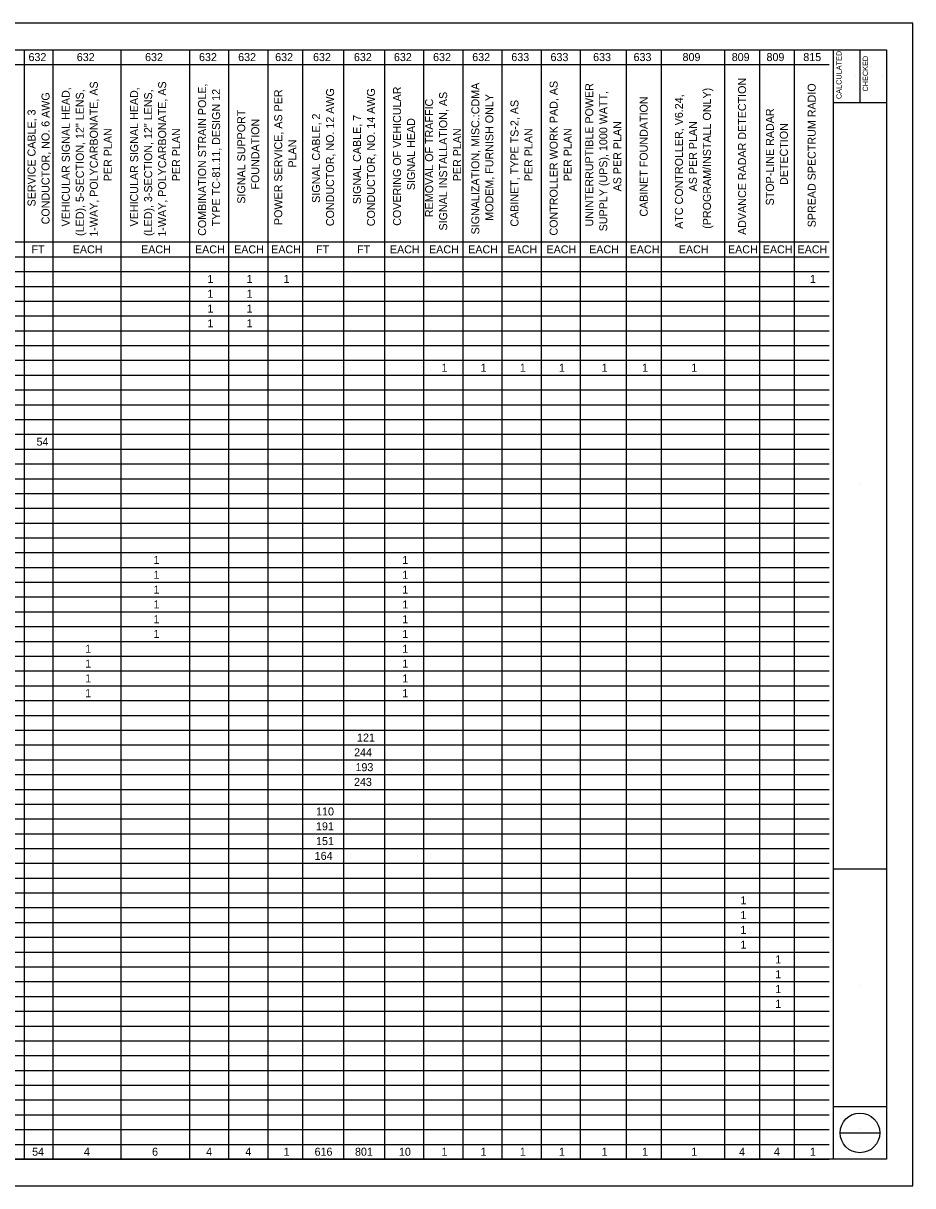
# Model space of a CAD drawing. Extents: x 43.5 to 77.5, y 34.1 to 56.1.
# Drawn here: x 60.62 to 77.46, y 34.09 to 56.09 of the extents above; entities that cross this region are included whole.
import ezdxf

# ---------------------------------------------------------------- set-up
doc = ezdxf.new("R2010")
doc.units = 0
for name, color, linetype in [('SH_Border', 7, 'Continuous'), ('SH_Cut_Line', 7, 'Continuous'), ('SH_Data', 7, 'Continuous'), ('SH_Text', 7, 'Continuous')]:
    doc.layers.add(name, color=color, linetype=linetype)

msp = doc.modelspace()

# ---------------------------------------------------------------- linework, layer by layer
at = {"layer": 'SH_Border'}
for p, q in [((45.459, 55.586), (75.875, 55.586)), ((60.642, 55.586), (60.642, 34.589)), ((61.186, 55.586), (61.186, 34.589)), ((62.47, 55.586), (62.47, 34.589)), ((63.771, 55.586), (63.771, 34.589)), ((64.512, 55.586), (64.512, 34.589)), ((65.253, 55.586), (65.253, 34.589)), ((65.912, 55.586), (65.912, 34.589)), ((66.686, 55.586), (66.686, 34.589)), ((67.46, 55.586), (67.46, 34.589)), ((68.201, 55.586), (68.201, 34.589)), ((68.942, 55.586), (68.942, 34.589)), ((69.683, 55.586), (69.683, 34.589)), ((70.424, 55.586), (70.424, 34.589)), ((71.165, 55.586), (71.165, 34.589)), ((72.038, 55.586), (72.038, 34.589)), ((72.697, 55.586), (72.697, 34.589)), ((73.899, 55.586), (73.899, 34.589)), ((74.558, 55.586), (74.558, 34.589)), ((75.216, 55.586), (75.216, 34.589)), ((75.959, 34.586), (75.959, 55.586)), ((76.459, 55.586), (76.459, 54.586)), ((52.029, 55.306), (75.875, 55.306)), ((75.959, 54.586), (76.959, 54.586)), ((52.029, 51.947), (75.875, 51.947)), ((45.459, 51.667), (75.875, 51.667)), ((45.459, 51.387), (75.875, 51.387)), ((45.459, 51.107), (75.875, 51.107)), ((45.459, 50.827), (75.875, 50.827)), ((45.459, 50.547), (75.875, 50.547)), ((45.459, 50.267), (75.875, 50.267)), ((45.459, 49.987), (75.875, 49.987)), ((45.459, 49.707), (75.875, 49.707)), ((45.459, 49.427), (75.875, 49.427)), ((45.459, 49.147), (75.875, 49.147)), ((45.459, 48.867), (75.875, 48.867)), ((45.459, 48.587), (75.875, 48.587)), ((45.459, 48.307), (75.875, 48.307)), ((45.459, 48.027), (75.875, 48.027)), ((45.459, 47.747), (75.875, 47.747)), ((45.459, 47.467), (75.875, 47.467)), ((45.459, 47.187), (75.875, 47.187)), ((45.459, 46.908), (75.875, 46.908)), ((45.459, 46.628), (75.875, 46.628)), ((45.459, 46.348), (75.875, 46.348)), ((45.459, 46.068), (75.875, 46.068)), ((45.459, 45.788), (75.875, 45.788)), ((45.459, 45.508), (75.875, 45.508)), ((45.459, 45.228), (75.875, 45.228)), ((45.459, 44.948), (75.875, 44.948)), ((45.459, 44.668), (75.875, 44.668)), ((45.459, 44.388), (75.875, 44.388)), ((45.459, 44.108), (75.875, 44.108)), ((45.459, 43.828), (75.875, 43.828)), ((45.459, 43.548), (75.875, 43.548)), ((45.459, 43.268), (75.875, 43.268)), ((45.459, 42.988), (75.875, 42.988)), ((45.459, 42.708), (75.875, 42.708)), ((45.459, 42.428), (75.875, 42.428)), ((45.459, 42.148), (75.875, 42.148)), ((45.459, 41.868), (75.875, 41.868)), ((45.459, 41.588), (75.875, 41.588)), ((45.459, 41.308), (75.875, 41.308)), ((45.459, 41.028), (75.875, 41.028)), ((45.459, 40.748), (75.875, 40.748)), ((45.459, 40.468), (75.875, 40.468)), ((45.459, 40.189), (75.875, 40.189)), ((75.959, 40.086), (76.959, 40.086)), ((45.459, 39.909), (75.875, 39.909)), ((45.459, 39.629), (75.875, 39.629)), ((45.459, 39.349), (75.875, 39.349)), ((45.459, 39.069), (75.875, 39.069)), ((45.459, 38.789), (75.875, 38.789)), ((45.459, 38.509), (75.875, 38.509)), ((45.459, 38.229), (75.875, 38.229)), ((45.459, 37.949), (75.875, 37.949)), ((45.459, 37.669), (75.875, 37.669)), ((45.459, 37.389), (75.875, 37.389)), ((45.459, 37.109), (75.875, 37.109)), ((45.459, 36.829), (75.875, 36.829)), ((45.459, 36.549), (75.875, 36.549)), ((45.459, 36.269), (75.875, 36.269)), ((45.459, 35.989), (75.875, 35.989)), ((45.459, 35.709), (75.875, 35.709)), ((45.459, 35.429), (75.875, 35.429)), ((75.959, 35.586), (76.959, 35.586)), ((45.459, 35.149), (75.875, 35.149)), ((45.459, 34.869), (75.875, 34.869)), ((45.459, 34.589), (75.875, 34.589))]:
    msp.add_line(p, q, dxfattribs=at)
msp.add_lwpolyline([(45.459, 55.586), (76.959, 55.586), (76.959, 34.586), (45.459, 34.586)], close=True, dxfattribs=at)
at = {"layer": 'SH_Cut_Line'}
msp.add_lwpolyline([(43.459, 34.086), (77.459, 34.086), (77.459, 56.086), (43.459, 56.086)], close=True, dxfattribs=at)
at = {"layer": 'SH_Data'}
for p, q in [((76.379, 55.09), (76.379, 55.09)), ((76.879, 55.09), (76.879, 55.09)), ((76.459, 47.378), (76.459, 47.378)), ((76.459, 37.878), (76.459, 37.878)), ((76.084, 35.086), (76.834, 35.086)), ((76.459, 35.171), (76.459, 35.171)), ((76.459, 34.831), (76.459, 34.831))]:
    msp.add_line(p, q, dxfattribs=at)
msp.add_circle((76.459, 35.086), 0.375, dxfattribs=at)

# ---------------------------------------------------------------- texts
for s, p in [('CALCULATED', (76.111, 54.651)), ('CHECKED', (76.611, 54.794))]:
    msp.add_text(s, height=0.1, rotation=90, dxfattribs=at).set_placement(p)
at = {"layer": 'SH_Text'}
for s, height, p in [('632', 0.1515, (60.724, 55.37)), ('632', 0.1515, (61.638, 55.37)), ('632', 0.1515, (62.93, 55.37)), ('632', 0.1515, (63.951, 55.37)), ('632', 0.1515, (64.692, 55.37)), ('632', 0.1515, (65.392, 55.37)), ('632', 0.1515, (66.109, 55.37)), ('632', 0.1515, (66.883, 55.37)), ('632', 0.1515, (67.64, 55.37)), ('632', 0.1515, (68.381, 55.37)), ('632', 0.1515, (69.122, 55.37)), ('633', 0.1515, (69.862, 55.37)), ('633', 0.1515, (70.603, 55.37)), ('633', 0.1515, (71.41, 55.37)), ('633', 0.1515, (72.175, 55.37)), ('809', 0.1515, (73.102, 55.37)), ('809', 0.1515, (74.033, 55.37)), ('809', 0.1515, (74.691, 55.37)), ('815', 0.1515, (75.387, 55.37)), ('FT', 0.1515, (60.781, 51.731)), ('EACH', 0.1515, (61.561, 51.731)), ('EACH', 0.1515, (62.854, 51.731)), ('EACH', 0.1515, (63.875, 51.731)), ('EACH', 0.1515, (64.616, 51.731)), ('EACH', 0.1515, (65.316, 51.731)), ('FT', 0.1515, (66.167, 51.731)), ('FT', 0.1515, (66.941, 51.731)), ('EACH', 0.1515, (67.564, 51.731)), ('EACH', 0.1515, (68.305, 51.731)), ('EACH', 0.1515, (69.046, 51.731)), ('EACH', 0.1515, (69.787, 51.731)), ('EACH', 0.1515, (70.528, 51.731)), ('EACH', 0.1515, (71.335, 51.731)), ('EACH', 0.1515, (72.101, 51.731)), ('EACH', 0.1515, (73.031, 51.731)), ('EACH', 0.1515, (73.962, 51.731)), ('EACH', 0.1515, (74.62, 51.731)), ('EACH', 0.1515, (75.279, 51.731)), ('1', 0.152, (64.11, 51.171)), ('1', 0.152, (64.851, 51.171)), ('1', 0.152, (65.551, 51.171)), ('1', 0.152, (75.514, 51.171)), ('1', 0.152, (64.11, 50.891)), ('1', 0.152, (64.851, 50.891)), ('1', 0.152, (64.11, 50.611)), ('1', 0.152, (64.851, 50.611)), ('1', 0.152, (64.11, 50.331)), ('1', 0.152, (64.851, 50.331)), ('1', 0.152, (68.54, 49.491)), ('1', 0.152, (69.281, 49.491)), ('1', 0.152, (70.022, 49.491)), ('1', 0.152, (70.763, 49.491)), ('1', 0.152, (71.57, 49.491)), ('1', 0.152, (72.336, 49.491)), ('1', 0.152, (73.266, 49.491)), ('54', 0.1515, (60.876, 48.092)), ('1', 0.152, (63.089, 45.852)), ('1', 0.152, (67.799, 45.852)), ('1', 0.152, (63.089, 45.572)), ('1', 0.152, (67.799, 45.572)), ('1', 0.152, (63.089, 45.292)), ('1', 0.152, (67.799, 45.292)), ('1', 0.152, (63.089, 45.012)), ('1', 0.152, (67.799, 45.012)), ('1', 0.152, (63.089, 44.732)), ('1', 0.152, (67.799, 44.732)), ('1', 0.152, (63.089, 44.452)), ('1', 0.152, (67.799, 44.452)), ('1', 0.152, (61.796, 44.172)), ('1', 0.152, (67.799, 44.172)), ('1', 0.152, (61.796, 43.892)), ('1', 0.152, (67.799, 43.892)), ('1', 0.152, (61.796, 43.612)), ('1', 0.152, (67.799, 43.612)), ('1', 0.152, (61.796, 43.332)), ('1', 0.152, (67.799, 43.332)), ('121', 0.1515, (66.941, 42.492)), ('244', 0.1515, (66.886, 42.212)), ('193', 0.1515, (66.912, 41.932)), ('243', 0.1515, (66.884, 41.653)), ('110', 0.1515, (66.167, 41.093)), ('191', 0.1515, (66.165, 40.813)), ('151', 0.1515, (66.166, 40.533)), ('164', 0.1515, (66.14, 40.253)), ('1', 0.152, (74.197, 39.413)), ('1', 0.152, (74.197, 39.133)), ('1', 0.152, (74.197, 38.853)), ('1', 0.152, (74.197, 38.573)), ('1', 0.152, (74.856, 38.293)), ('1', 0.152, (74.856, 38.013)), ('1', 0.152, (74.856, 37.733)), ('1', 0.152, (74.856, 37.453)), ('54', 0.1515, (60.792, 34.654)), ('4', 0.152, (61.772, 34.654)), ('6', 0.152, (63.062, 34.654)), ('4', 0.152, (64.086, 34.654)), ('4', 0.152, (64.827, 34.654)), ('1', 0.152, (65.551, 34.654)), ('616', 0.1515, (66.138, 34.654)), ('801', 0.1515, (66.903, 34.654)), ('10', 0.1515, (67.735, 34.654)), ('1', 0.152, (68.54, 34.654)), ('1', 0.152, (69.281, 34.654)), ('1', 0.152, (70.022, 34.654)), ('1', 0.152, (70.763, 34.654)), ('1', 0.152, (71.57, 34.654)), ('1', 0.152, (72.336, 34.654)), ('1', 0.152, (73.266, 34.654)), ('4', 0.152, (74.172, 34.654)), ('4', 0.152, (74.831, 34.654)), ('1', 0.152, (75.514, 34.654))]:
    msp.add_text(s, height=height, dxfattribs=at).set_placement(p)
for s, height, p in [('ADVANCE RADAR DETECTION', 0.15151, (74.304, 52.081)), ('VEHICULAR SIGNAL HEAD,', 0.15151, (61.506, 52.24)), ('(LED), 5-SECTION, 12" LENS,', 0.15151, (61.771, 52.061)), ('1-WAY, POLYCARBONATE, AS', 0.15151, (62.036, 52.048)), ('VEHICULAR SIGNAL HEAD,', 0.15151, (62.799, 52.24)), ('(LED), 3-SECTION, 12" LENS,', 0.15151, (63.064, 52.06)), ('1-WAY, POLYCARBONATE, AS', 0.15151, (63.329, 52.048)), ('COMBINATION STRAIN POLE,', 0.15151, (64.085, 52.063)), ('TYPE TC-81.11, DESIGN 12', 0.15151, (64.35, 52.242)), ('POWER SERVICE, AS PER', 0.15151, (65.526, 52.267)), ('CONDUCTOR, NO. 12 AWG', 0.15151, (66.507, 52.246)), ('CONDUCTOR, NO. 14 AWG', 0.15151, (67.281, 52.245)), ('COVERING OF VEHICULAR', 0.15151, (67.774, 52.253)), ('SIGNALIZATION, MISC.:CDMA', 0.15151, (69.256, 52.09)), ('CONTROLLER WORK PAD, AS', 0.15151, (70.738, 52.068)), ('UNINTERRUPTIBLE POWER', 0.15151, (71.412, 52.24)), ('SUPPLY (UPS), 1000 WATT,', 0.15151, (71.677, 52.148)), ('(PROGRAM/INSTALL ONLY)', 0.15151, (73.639, 52.196)), ('SPREAD SPECTRUM RADIO', 0.15151, (75.622, 52.224)), ('CONDUCTOR, NO. 6 AWG', 0.15151, (61.122, 52.28)), ('REMOVAL OF TRAFFIC', 0.15151, (68.382, 52.417)), ('SIGNAL INSTALLATION, AS', 0.15151, (68.647, 52.164)), ('MODEM, FURNISH ONLY', 0.15151, (69.521, 52.348)), ('CABINET, TYPE TS-2, AS', 0.15151, (69.997, 52.237)), ('CABINET FOUNDATION', 0.15151, (72.443, 52.427)), ('ATC CONTROLLER, V6.24,', 0.15151, (73.109, 52.196)), ('SERVICE CABLE, 3', 0.15151, (60.857, 52.619)), ('SIGNAL SUPPORT', 0.15151, (64.826, 52.672)), ('SIGNAL CABLE, 2', 0.15151, (66.242, 52.688)), ('SIGNAL CABLE, 7', 0.15151, (67.016, 52.663)), ('STOP-LINE RADAR', 0.15151, (74.83, 52.639)), ('FOUNDATION', 0.1515, (65.091, 52.939)), ('SIGNAL HEAD', 0.15151, (68.039, 52.928)), ('AS PER PLAN', 0.15151, (71.943, 52.904)), ('AS PER PLAN', 0.15151, (73.374, 52.904)), ('DETECTION', 0.1515, (75.095, 53.025)), ('PER PLAN', 0.1515, (62.301, 53.096)), ('PER PLAN', 0.1515, (63.594, 53.096)), ('PER PLAN', 0.1515, (68.912, 53.096)), ('PER PLAN', 0.1515, (70.262, 53.096)), ('PER PLAN', 0.1515, (71.003, 53.096)), ('PLAN', 0.1515, (65.791, 53.355))]:
    msp.add_text(s, height=height, rotation=90, dxfattribs=at).set_placement(p)

doc.saveas('drawing.dxf')
